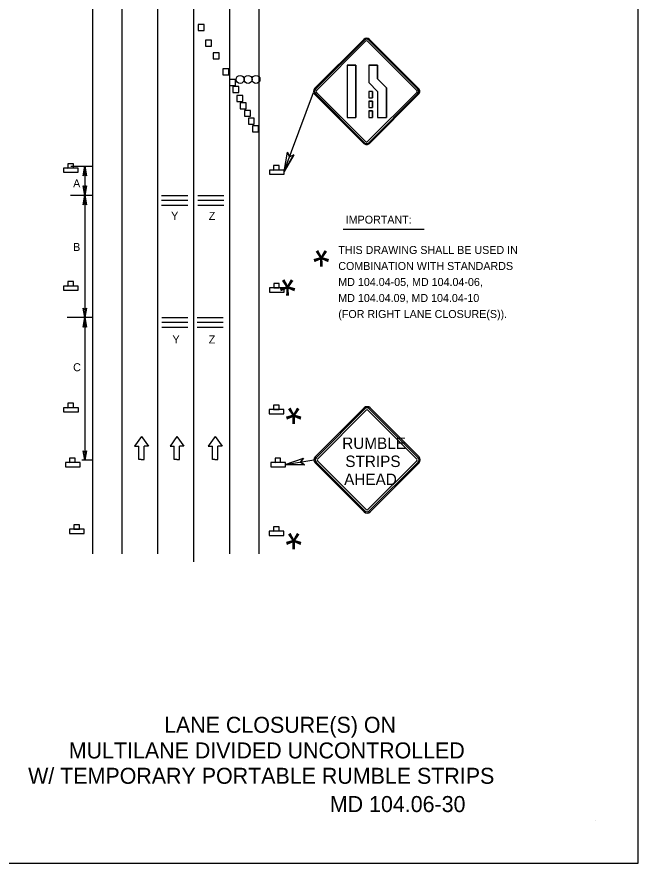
# Model space of a CAD drawing. Extents: x 0 to 1549163, y -476626 to 622136.
# Drawn here: x 15.28 to 19.94, y 5.67 to 12.01 of the extents above; entities that cross this region are included whole.
import ezdxf

# ---------------------------------------------------------------- set-up
doc = ezdxf.new("R2010")
doc.units = 0
for name, color, linetype in [('BORD-LINE', 7, 'Continuous'), ('DETL-DIMS', 7, 'Continuous'), ('DETL-LINE', 7, 'Continuous'), ('DETL-NOTE', 7, 'Continuous'), ('DETL-TITL', 7, 'Continuous'), ('SIGN-FACE_P', 7, 'Continuous'), ('TTLB-TEXT', 7, 'Continuous'), ('USER-BORD', 7, 'Continuous'), ('USER-CLIP', 7, 'Continuous')]:
    doc.layers.add(name, color=color, linetype=linetype)

# ---------------------------------------------------------------- blocks, each defined once
blk = doc.blocks.new('PANEL0')
at = {"layer": 'USER-BORD'}
for centre in [(0.00309, -0.00012), (0.00928, -0.00012), (0.01546, -0.00012)]:
    blk.add_circle(centre, 0.00312, dxfattribs=at)
blk = doc.blocks.new('TD')
at = {"layer": 'USER-BORD'}
for p, q in [((0, 0), (-0.0054, -0.0077)), ((0, 0), (0.0054, -0.0077)), ((-0.0054, -0.0077), (-0.0021, -0.0077)), ((-0.0021, -0.018), (-0.0021, -0.0077)), ((0.0021, -0.018), (0.0021, -0.0077)), ((0.0054, -0.0077), (0.0021, -0.0077)), ((-0.0002, -0.018), (-0.0021, -0.018)), ((-0.0002, -0.018), (0.0002, -0.018)), ((0.0002, -0.018), (0.0021, -0.018))]:
    blk.add_line(p, q, dxfattribs=at)
blk = doc.blocks.new('SIGN15')
at = {"layer": 'USER-BORD'}
for points in [[(-0.0013, 0.0018), (0.0011, 0.0019), (0.0011, 0.0037), (-0.0013, 0.0037)], [(-0.0031, 0.0018), (-0.0031, 0), (0.0032, 0), (0.0032, 0.0018)]]:
    blk.add_lwpolyline(points, close=True, dxfattribs=at)

msp = doc.modelspace()

# ---------------------------------------------------------------- linework, layer by layer
at = {"layer": 'DETL-DIMS'}
for p, q in [((17.2845, 10.8524), (17.505, 11.4415)), ((17.2831, 10.8501), (17.3094, 10.9928)), ((17.2831, 10.8501), (17.3568, 10.9752)), ((17.3236, 10.9588), (17.3094, 10.9928)), ((17.3568, 10.9752), (17.3236, 10.9588)), ((15.8482, 10.8875), (15.6835, 10.8875)), ((15.7885, 10.8884), (15.7759, 10.8169)), ((15.7885, 10.8884), (15.8011, 10.8169)), ((15.7887, 10.8839), (15.7889, 8.6851)), ((15.7759, 10.8169), (15.7885, 10.8304)), ((15.7885, 10.8304), (15.8011, 10.8169)), ((15.7886, 10.6698), (15.776, 10.7413)), ((15.7886, 10.7278), (15.776, 10.7413)), ((15.7886, 10.6698), (15.8012, 10.7413)), ((15.8012, 10.7413), (15.7886, 10.7278)), ((15.8482, 10.6698), (15.6828, 10.6698)), ((15.7885, 10.6707), (15.7759, 10.5992)), ((15.7885, 10.6707), (15.8011, 10.5992)), ((15.7759, 10.5992), (15.7885, 10.6127)), ((15.7885, 10.6127), (15.8011, 10.5992)), ((15.7889, 9.7545), (15.7763, 9.826)), ((15.7889, 9.8125), (15.7763, 9.826)), ((15.7889, 9.7545), (15.8015, 9.826)), ((15.8015, 9.826), (15.7889, 9.8125)), ((15.8482, 9.7545), (15.6574, 9.7545)), ((15.7885, 9.7554), (15.7759, 9.6839)), ((15.7885, 9.7554), (15.8011, 9.6839)), ((15.7759, 9.6839), (15.7885, 9.6974)), ((15.7885, 9.6974), (15.8011, 9.6839)), ((15.7889, 8.6851), (15.7763, 8.7566)), ((15.7889, 8.7431), (15.7763, 8.7566)), ((15.7889, 8.6851), (15.8015, 8.7566)), ((15.8015, 8.7566), (15.7889, 8.7431)), ((17.2925, 8.6533), (17.4295, 8.7013)), ((17.2947, 8.6534), (17.5078, 8.6887)), ((17.4069, 8.6721), (17.4295, 8.7013)), ((15.8479, 8.6851), (15.7679, 8.6851)), ((17.2925, 8.6533), (17.4377, 8.6514)), ((17.4377, 8.6514), (17.4069, 8.6721))]:
    msp.add_line(p, q, dxfattribs=at)
for points in [[(17.3568, 10.9752), (17.2831, 10.8501), (17.3094, 10.9928), (17.3236, 10.9588)], [(15.7759, 10.8169), (15.7885, 10.8884), (15.8011, 10.8169), (15.7885, 10.8304)], [(15.8012, 10.7413), (15.7886, 10.6698), (15.776, 10.7413), (15.7886, 10.7278)], [(15.7759, 10.5992), (15.7885, 10.6707), (15.8011, 10.5992), (15.7885, 10.6127)], [(15.8015, 9.826), (15.7889, 9.7545), (15.7763, 9.826), (15.7889, 9.8125)], [(15.7759, 9.6839), (15.7885, 9.7554), (15.8011, 9.6839), (15.7885, 9.6974)], [(15.8015, 8.7566), (15.7889, 8.6851), (15.7763, 8.7566), (15.7889, 8.7431)], [(17.4377, 8.6514), (17.2925, 8.6533), (17.4295, 8.7013), (17.4069, 8.6721)]]:
    msp.add_lwpolyline(points, close=True, dxfattribs=at)
at = {"layer": 'DETL-LINE'}
for p, q in [((16.3341, 16.3778), (16.3341, 8.4351)), ((15.8482, 15.9277), (15.8482, 7.985)), ((16.0672, 15.9278), (16.0672, 7.9851)), ((16.0673, 15.9277), (16.0673, 7.985)), ((16.3341, 15.9278), (16.3341, 7.9851)), ((16.6039, 15.9278), (16.6039, 7.9851)), ((16.6039, 15.9278), (16.6039, 7.9851)), ((16.8736, 15.9278), (16.8736, 7.9851)), ((17.0935, 15.9278), (17.0935, 7.9851)), ((16.6039, 15.8673), (16.6039, 7.9246)), ((17.5126, 11.4709), (17.8808, 11.839)), ((17.5181, 11.4655), (17.8862, 11.8336)), ((17.5266, 11.457), (17.8947, 11.8251)), ((17.9094, 11.8251), (18.2783, 11.457)), ((17.918, 11.8336), (18.2869, 11.4655)), ((17.9234, 11.839), (18.2923, 11.4709)), ((17.7556, 11.645), (17.7556, 11.2543)), ((17.7556, 11.645), (17.8212, 11.645)), ((17.8212, 11.645), (17.7556, 11.645)), ((17.7556, 11.645), (17.7556, 11.2543)), ((17.8212, 11.645), (17.8212, 11.2543)), ((17.8212, 11.2543), (17.8212, 11.645)), ((17.9181, 11.645), (17.9181, 11.516)), ((17.9181, 11.645), (17.9838, 11.645)), ((17.9838, 11.645), (17.9181, 11.645)), ((17.9181, 11.645), (17.9181, 11.516)), ((17.9838, 11.645), (17.9838, 11.5432)), ((17.9838, 11.5432), (17.9838, 11.645)), ((18.0502, 11.4768), (17.9838, 11.5432)), ((18.0502, 11.4768), (17.9838, 11.5432)), ((17.9845, 11.4496), (17.9181, 11.516)), ((17.9181, 11.516), (17.9845, 11.4496)), ((18.0502, 11.4768), (18.0502, 11.2543)), ((18.0502, 11.2543), (18.0502, 11.4768)), ((17.8808, 11.0594), (17.5126, 11.4283)), ((17.8862, 11.0648), (17.5181, 11.4337)), ((17.8947, 11.0733), (17.5266, 11.4422)), ((18.2783, 11.4422), (17.9094, 11.0733)), ((18.2869, 11.4337), (17.918, 11.0648)), ((17.9181, 11.4496), (17.9181, 11.4008)), ((17.9471, 11.4496), (17.9181, 11.4496)), ((17.9181, 11.4496), (17.9181, 11.4008)), ((18.2923, 11.4283), (17.9234, 11.0594)), ((17.9471, 11.4496), (17.9471, 11.4008)), ((17.9471, 11.4008), (17.9471, 11.4496)), ((17.9845, 11.4496), (17.9845, 11.2543)), ((17.9845, 11.4496), (17.9845, 11.2543)), ((17.9181, 11.4008), (17.9471, 11.4008)), ((17.9181, 11.4008), (17.9471, 11.4008)), ((17.9181, 11.3764), (17.9471, 11.3764)), ((17.9181, 11.3764), (17.9181, 11.3275)), ((17.9471, 11.3764), (17.9181, 11.3764)), ((17.9181, 11.3764), (17.9181, 11.3275)), ((17.9471, 11.3764), (17.9471, 11.3275)), ((17.9471, 11.3275), (17.9471, 11.3764)), ((17.9181, 11.3275), (17.9471, 11.3275)), ((17.9181, 11.3275), (17.9471, 11.3275)), ((17.9181, 11.3031), (17.9471, 11.3031)), ((17.9181, 11.3031), (17.9181, 11.2543)), ((17.9471, 11.3031), (17.9181, 11.3031)), ((17.9181, 11.3031), (17.9181, 11.2543)), ((17.9471, 11.3031), (17.9471, 11.2543)), ((17.9471, 11.2543), (17.9471, 11.3031)), ((17.7556, 11.2543), (17.8212, 11.2543)), ((17.7556, 11.2543), (17.8212, 11.2543)), ((17.9181, 11.2543), (17.9471, 11.2543)), ((17.9181, 11.2543), (17.9471, 11.2543)), ((17.9845, 11.2543), (18.0502, 11.2543)), ((17.9845, 11.2543), (18.0502, 11.2543)), ((16.3655, 10.6701), (16.5616, 10.6701)), ((16.6361, 10.6701), (16.8322, 10.6701)), ((16.3655, 10.6348), (16.5616, 10.6348)), ((16.3655, 10.5969), (16.5616, 10.5969)), ((16.6361, 10.6348), (16.8322, 10.6348)), ((16.6361, 10.5969), (16.8322, 10.5969)), ((16.3658, 9.7564), (16.5619, 9.7564)), ((16.3658, 9.7211), (16.5619, 9.7211)), ((16.6311, 9.7564), (16.8272, 9.7564)), ((16.6311, 9.7211), (16.8272, 9.7211)), ((16.3658, 9.6832), (16.5619, 9.6832)), ((16.6311, 9.6832), (16.8272, 9.6832))]:
    msp.add_line(p, q, dxfattribs=at)
for points in [[(16.3342, 11.934), (16.3342, 11.8777)], [(16.604, 11.934), (16.604, 11.8777)], [(16.3342, 11.8777), (16.3342, 11.8215)], [(16.604, 11.8777), (16.604, 11.8215)], [(16.3342, 11.484), (16.3342, 11.4277)], [(16.604, 11.484), (16.604, 11.4277)], [(16.3342, 11.4277), (16.3342, 11.3715)], [(16.604, 11.4277), (16.604, 11.3715)], [(16.3342, 11.034), (16.3342, 10.9777)], [(16.604, 11.034), (16.604, 10.9777)], [(16.3342, 10.9777), (16.3342, 10.9215)], [(16.604, 10.9777), (16.604, 10.9215)], [(16.3342, 10.584), (16.3342, 10.5277)], [(16.3342, 10.5277), (16.3342, 10.4715)], [(16.604, 10.584), (16.604, 10.5277)], [(16.604, 10.5277), (16.604, 10.4715)], [(16.3342, 10.134), (16.3342, 10.0777)], [(16.604, 10.134), (16.604, 10.0777)], [(16.3342, 10.0777), (16.3342, 10.0215)], [(16.604, 10.0777), (16.604, 10.0215)], [(16.3342, 9.684), (16.3342, 9.6277)], [(16.604, 9.684), (16.604, 9.6277)], [(16.3342, 9.6277), (16.3342, 9.5715)], [(16.604, 9.6277), (16.604, 9.5715)], [(16.3342, 9.234), (16.3342, 9.1777)], [(16.604, 9.234), (16.604, 9.1777)], [(16.3342, 9.1777), (16.3342, 9.1215)], [(16.604, 9.1777), (16.604, 9.1215)], [(16.3342, 8.784), (16.3342, 8.7277)], [(16.604, 8.784), (16.604, 8.7277)], [(16.3342, 8.7277), (16.3342, 8.6715)], [(16.604, 8.7277), (16.604, 8.6715)], [(16.3342, 8.334), (16.3342, 8.2777)], [(16.604, 8.334), (16.604, 8.2777)], [(16.3342, 8.2777), (16.3342, 8.2215)], [(16.604, 8.2777), (16.604, 8.2215)]]:
    msp.add_lwpolyline(points, dxfattribs=at)
for points in [[(16.6403, 11.9054), (16.6851, 11.9054), (16.6851, 11.9502), (16.6403, 11.9502)], [(16.6944, 11.7885), (16.7392, 11.7885), (16.7392, 11.8333), (16.6944, 11.8333)], [(16.752, 11.6927), (16.7968, 11.6927), (16.7968, 11.7375), (16.752, 11.7375)], [(16.8243, 11.5741), (16.8691, 11.5741), (16.8691, 11.6189), (16.8243, 11.6189)], [(16.8741, 11.4932), (16.9189, 11.4932), (16.9189, 11.538), (16.8741, 11.538)], [(16.8991, 11.44), (16.9439, 11.44), (16.9439, 11.4848), (16.8991, 11.4848)], [(16.9297, 11.3741), (16.9745, 11.3741), (16.9745, 11.4189), (16.9297, 11.4189)], [(16.9541, 11.3187), (16.9989, 11.3187), (16.9989, 11.3635), (16.9541, 11.3635)], [(16.9871, 11.2625), (17.0319, 11.2625), (17.0319, 11.3073), (16.9871, 11.3073)], [(17.0156, 11.2034), (17.0604, 11.2034), (17.0604, 11.2482), (17.0156, 11.2482)], [(17.0473, 11.1474), (17.0921, 11.1474), (17.0921, 11.1922), (17.0473, 11.1922)]]:
    msp.add_lwpolyline(points, close=True, dxfattribs=at)
for centre, radius, start, end in [((17.9021, 11.8175), 0.0303, 45.05999, 135), ((17.9021, 11.818), 0.0223, 45.05999, 135), ((17.9021, 11.8182), 0.0101, 45.05999, 135), ((17.5341, 11.4496), 0.0303, 135, 224.93988), ((17.5337, 11.4496), 0.0223, 135, 224.93988), ((17.5335, 11.4496), 0.0101, 135, 224.93988), ((18.2714, 11.4496), 0.0101, 315, 45.06012), ((18.2712, 11.4496), 0.0223, 315, 45.06012), ((18.2708, 11.4496), 0.0303, 315, 45.06012), ((17.9021, 11.0809), 0.0303, 224.94001, 315), ((17.9021, 11.0804), 0.0223, 224.94001, 315), ((17.9021, 11.0802), 0.0101, 224.94001, 315)]:
    msp.add_arc(centre, radius, start, end, dxfattribs=at)
at = {"layer": 'DETL-NOTE'}
msp.add_line((17.7261, 10.4176), (18.334, 10.4176), dxfattribs=at)
at = {"layer": 'DETL-TITL'}
for p, q in [((17.8832, 9.0779), (17.5169, 8.7115)), ((17.8896, 9.0712), (17.5233, 8.7049)), ((18.2889, 8.7049), (17.9225, 9.0712)), ((18.2955, 8.7115), (17.9292, 9.0779)), ((17.5335, 8.6947), (17.8998, 9.061)), ((17.9124, 9.061), (18.2787, 8.6947)), ((17.5169, 8.6653), (17.8832, 8.2993)), ((17.5233, 8.672), (17.8896, 8.3057)), ((17.8998, 8.3159), (17.5335, 8.6822)), ((18.2787, 8.6822), (17.9124, 8.3159)), ((17.9225, 8.3057), (18.2889, 8.672)), ((17.9292, 8.2993), (18.2955, 8.6653))]:
    msp.add_line(p, q, dxfattribs=at)
for centre, radius, start, end in [((17.9061, 9.0547), 0.0324, 45, 135), ((17.9061, 9.0547), 0.0233, 45, 135), ((17.9061, 9.0547), 0.00886, 45, 135), ((17.5398, 8.6884), 0.0324, 135, 225), ((17.5398, 8.6884), 0.0233, 135, 225), ((17.5398, 8.6884), 0.00886, 135, 225), ((18.2724, 8.6884), 0.00886, 315, 45), ((18.2724, 8.6884), 0.0233, 315, 45), ((18.2724, 8.6884), 0.0324, 315, 45), ((17.9061, 8.3221), 0.0233, 225, 315), ((17.9061, 8.3221), 0.00886, 225, 315), ((17.9061, 8.3221), 0.0324, 225, 315)]:
    msp.add_arc(centre, radius, start, end, dxfattribs=at)
at = {"layer": 'TTLB-TEXT'}
msp.add_line((19.6208, 5.9844), (19.6208, 5.9844), dxfattribs=at)
at = {"layer": 'USER-CLIP'}
msp.add_lwpolyline([(19.9377, 16.6675), (11.4377, 16.6675), (11.4377, 5.6675), (19.9377, 5.6675)], close=True, dxfattribs=at)

# ---------------------------------------------------------------- block references
at = {"layer": 'DETL-LINE'}
for name, p, xscale, yscale in [('PANEL0', (16.9245, 11.5398), 9.6, 9.6), ('SIGN15', (15.6845, 10.8429), 17.523809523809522, 17.523809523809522), ('SIGN15', (17.2275, 10.8285), 17.523809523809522, 17.523809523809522), ('SIGN15', (15.6845, 9.9589), 17.523809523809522, 17.523809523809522), ('SIGN15', (17.2285, 9.9451), 17.523809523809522, 17.523809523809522), ('SIGN15', (15.6852, 9.0478), 17.523809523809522, 17.523809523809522), ('SIGN15', (17.2266, 9.0334), 17.523809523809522, 17.523809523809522), ('TD', (16.2145, 8.8639), 9.6, 9.6), ('TD', (16.4804, 8.8639), 9.6, 9.6), ('TD', (16.7665, 8.8639), 9.6, 9.6), ('SIGN15', (15.6986, 8.6375), 17.523809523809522, 17.523809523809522), ('SIGN15', (17.2386, 8.6376), 17.523809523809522, 17.523809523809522), ('SIGN15', (15.7296, 8.1371), 17.523809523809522, 17.523809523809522), ('SIGN15', (17.2266, 8.1227), 17.523809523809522, 17.523809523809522)]:
    msp.add_blockref(name, p, dxfattribs=dict(at, xscale=xscale, yscale=yscale))

# ---------------------------------------------------------------- texts
at = {"layer": 'BORD-LINE'}
msp.add_text('HDVBARREIRA', height=6e-12, rotation=180, dxfattribs=at).set_placement((19.6208, 7.4352))
at = {"layer": 'DETL-NOTE'}
for s, p in [('A', (15.7019, 10.7306)), ('Y', (16.4365, 10.487)), ('Z', (16.7189, 10.4866)), ('IMPORTANT:', (17.7456, 10.4584)), ('B', (15.7019, 10.2535)), ('THIS DRAWING SHALL BE USED IN ', (17.6899, 10.2313)), ('COMBINATION WITH STANDARDS', (17.6899, 10.1113)), ('MD 104.04-05, MD 104.04-06, ', (17.6899, 9.9913)), ('MD 104.04.09, MD 104.04-10', (17.6899, 9.8713)), ('(FOR RIGHT LANE CLOSURE(S)).', (17.6899, 9.7513)), ('Y', (16.4467, 9.5609)), ('Z', (16.7187, 9.5609)), ('C', (15.7019, 9.3526))]:
    msp.add_text(s, height=0.06, dxfattribs=at).set_placement(p)
for p in [(17.6257, 10.3794), (17.3727, 10.1608), (17.4187, 9.1991), (17.4187, 8.2603)]:
    msp.add_text('*', height=0.2421, rotation=180, dxfattribs=at).set_placement(p)
at = {"layer": 'SIGN-FACE_P'}
for s, p in [('RUMBLE', (17.7195, 8.7703)), ('STRIPS', (17.7427, 8.635)), ('AHEAD', (17.7337, 8.4997))]:
    msp.add_text(s, height=0.08572, dxfattribs=at).set_placement(p)
at = {"layer": 'TTLB-TEXT'}
for s, p in [('LANE CLOSURE(S) ON', (16.3838, 6.6435)), ('MULTILANE DIVIDED UNCONTROLLED', (15.6692, 6.4516)), ('W/ TEMPORARY PORTABLE RUMBLE STRIPS', (15.3646, 6.2615)), ('MD 104.06-30', (17.6266, 6.0498))]:
    msp.add_text(s, height=0.12, dxfattribs=at).set_placement(p)

doc.saveas('drawing.dxf')
